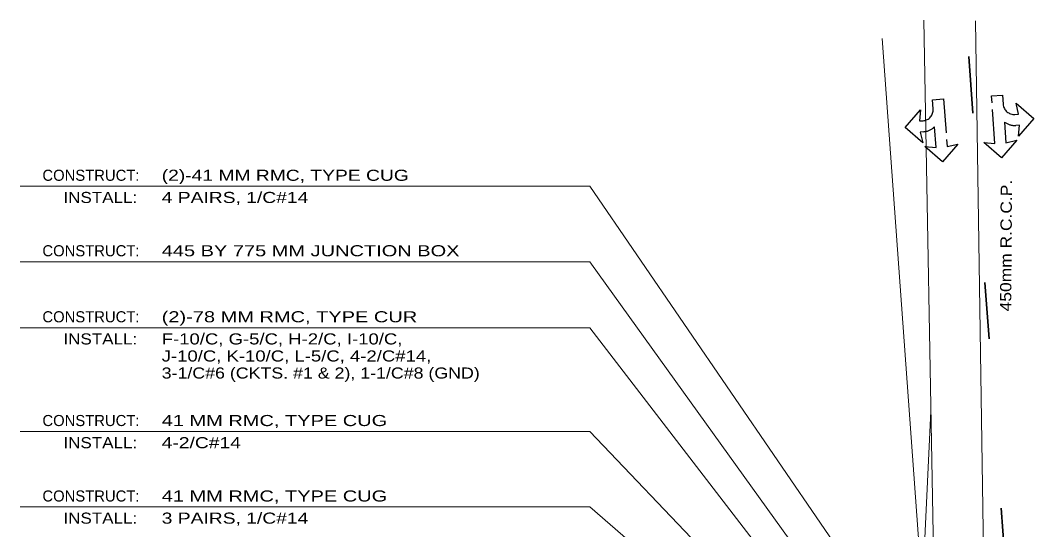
# Model space of a CAD drawing. Extents: x 168203 to 169864, y 223196 to 223870.
# Drawn here: x 168291.9 to 168345.6, y 223676.6 to 223703.6 of the extents above; entities that cross this region are included whole.
import ezdxf
from ezdxf.enums import TextEntityAlignment as Align

# ---------------------------------------------------------------- set-up
doc = ezdxf.new("R2010")
doc.units = 0
doc.header["$LTSCALE"] = 0.3
doc.linetypes.add('LONG_DASH_SHORT_DASH', pattern=[9.9, 6, -1.2, 1.5, -1.2])
for name, color, linetype, lineweight in [('1', 7, 'Continuous', 13), ('10', 7, 'Continuous', 13), ('23', 7, 'Continuous', 25), ('36', 7, 'Continuous', 35)]:
    doc.layers.add(name, color=color, linetype=linetype, lineweight=lineweight)

msp = doc.modelspace()

# ---------------------------------------------------------------- linework, layer by layer
at = {"layer": '1'}
msp.add_line((168337.5591, 223702.6003), (168340.1802, 223666.3325), dxfattribs=at)
at = {"layer": '10'}
for p, q in [((168322.0601, 223694.7617), (168291.8523, 223694.7617)), ((168322.0601, 223690.7617), (168291.8523, 223690.7617)), ((168338.5814, 223667.7744), (168322.0601, 223690.7617)), ((168322.0601, 223687.2617), (168291.8523, 223687.2617)), ((168322.0601, 223681.7617), (168291.8523, 223681.7617)), ((168338.7228, 223664.3092), (168322.0601, 223681.7617)), ((168322.0601, 223677.7617), (168291.8523, 223677.7617))]:
    msp.add_line(p, q, dxfattribs=at)
for points in [[(168339.6341, 223667.9144), (168339.5071, 223669.2948), (168322.0601, 223694.7617)], [(168340.4145, 223662.1242), (168340.5555, 223663.2103), (168322.0601, 223687.2617)], [(168338.5925, 223660.394), (168339.2821, 223662.7976), (168322.0601, 223677.7617)]]:
    msp.add_lwpolyline(points, dxfattribs=at)
at = {"layer": '23', "lineweight": 13}
for p, q in [((168340.3639, 223670.3485), (168339.7699, 223703.561)), ((168342.502, 223703.5394), (168343.1919, 223658.702)), ((168340.1403, 223682.8465), (168337.0072, 223618.1402))]:
    msp.add_line(p, q, dxfattribs=at)
at = {"layer": '36'}
for p, q in [((168342.358, 223698.6402), (168342.1417, 223701.6325)), ((168343.223, 223686.6715), (168343.0067, 223689.6637)), ((168345.3131, 223657.7471), (168343.8716, 223677.695))]:
    msp.add_line(p, q, dxfattribs=at)
at = {"layer": '36', "linetype": 'LONG_DASH_SHORT_DASH', "lineweight": 25}
for points in [[(168340.8103, 223699.3908), (168340.9932, 223696.8615), (168341.5698, 223697.0009), (168340.7576, 223696.0621), (168339.8188, 223696.8743), (168340.4095, 223696.8193), (168340.3301, 223697.9178)], [(168340.2618, 223698.8621), (168340.2266, 223699.3486), (168340.8103, 223699.3908)], [(168344.0397, 223698.1682), (168344.1192, 223697.0697), (168344.6958, 223697.2091), (168343.8836, 223696.2703), (168342.9448, 223697.0825), (168343.5355, 223697.0275), (168343.3526, 223699.5568), (168343.9363, 223699.599), (168343.9715, 223699.1125)], [(168339.7625, 223697.6526), (168339.5679, 223697.6385), (168339.7074, 223697.0619), (168338.7686, 223697.8741), (168339.5808, 223698.8129), (168339.5257, 223698.2222), (168339.7203, 223698.2363)], [(168344.5973, 223698.5711), (168344.7919, 223698.5851), (168344.6525, 223699.1618)], [(168344.6525, 223699.1618), (168345.5913, 223698.3496), (168344.7791, 223697.4107), (168344.8341, 223698.0015), (168344.6395, 223697.9874)]]:
    msp.add_lwpolyline(points, dxfattribs=at)
for centre, radius, start, end in [((168339.6781, 223698.82), 0.5852, 274.13538, 4.13538), ((168344.5552, 223699.1548), 0.5852, 184.13538, 274.13538), ((168339.6992, 223698.5281), 0.8778, 274.13538, 315.94484), ((168344.5763, 223698.8629), 0.8778, 232.32592, 274.13538)]:
    msp.add_arc(centre, radius, start, end, dxfattribs=at)

# ---------------------------------------------------------------- texts
at = {"layer": '10'}
for p in [(168293.027, 223695.0509), (168293.027, 223691.0509), (168293.027, 223687.5509), (168293.027, 223682.0509), (168293.027, 223678.0509)]:
    msp.add_text('CONSTRUCT:', height=0.5873, dxfattribs=at).set_placement(p)
for s, width, p in [('(2)-41 MM RMC, TYPE CUG              ', 1.3, (168299.3523, 223695.0509)), ('4 PAIRS, 1/C#14                      ', 1.3, (168299.3523, 223693.8762)), ('445 BY 775 MM JUNCTION BOX           ', 1.35, (168299.3523, 223691.0509)), ('(2)-78 MM RMC, TYPE CUR                ', 1.35, (168299.3523, 223687.5509)), ('F-10/C, G-5/C, H-2/C, I-10/C,', 1.25, (168299.3523, 223686.3762)), ('J-10/C, K-10/C, L-5/C, 4-2/C#14, ', 1.25, (168299.3523, 223685.4725)), ('3-1/C#6 (CKTS. #1 & 2), 1-1/C#8 (GND) ', 1.2, (168299.3523, 223684.5689)), ('41 MM RMC, TYPE CUG              ', 1.35, (168299.3523, 223682.0509)), ('4-2/C#14                             ', 1.3, (168299.3523, 223680.8762)), ('41 MM RMC, TYPE CUG              ', 1.35, (168299.3523, 223678.0509)), ('3 PAIRS, 1/C#14                      ', 1.3, (168299.3523, 223676.8762))]:
    msp.add_text(s, height=0.5873, dxfattribs=dict(at, width=width)).set_placement(p)
at = {"layer": '10', "width": 1.15}
for p in [(168298.0542, 223693.8762), (168298.0542, 223686.3762), (168298.0542, 223680.8762), (168298.0542, 223676.8762)]:
    msp.add_text('INSTALL:', height=0.5873, dxfattribs=at).set_placement(p, align=Align.RIGHT)
at = {"layer": '23', "width": 1.15}
msp.add_text('450mm R.C.C.P.', height=0.6, rotation=89.633, dxfattribs=at).set_placement((168344.4197, 223691.6166), align=Align.CENTER)

doc.saveas('drawing.dxf')
